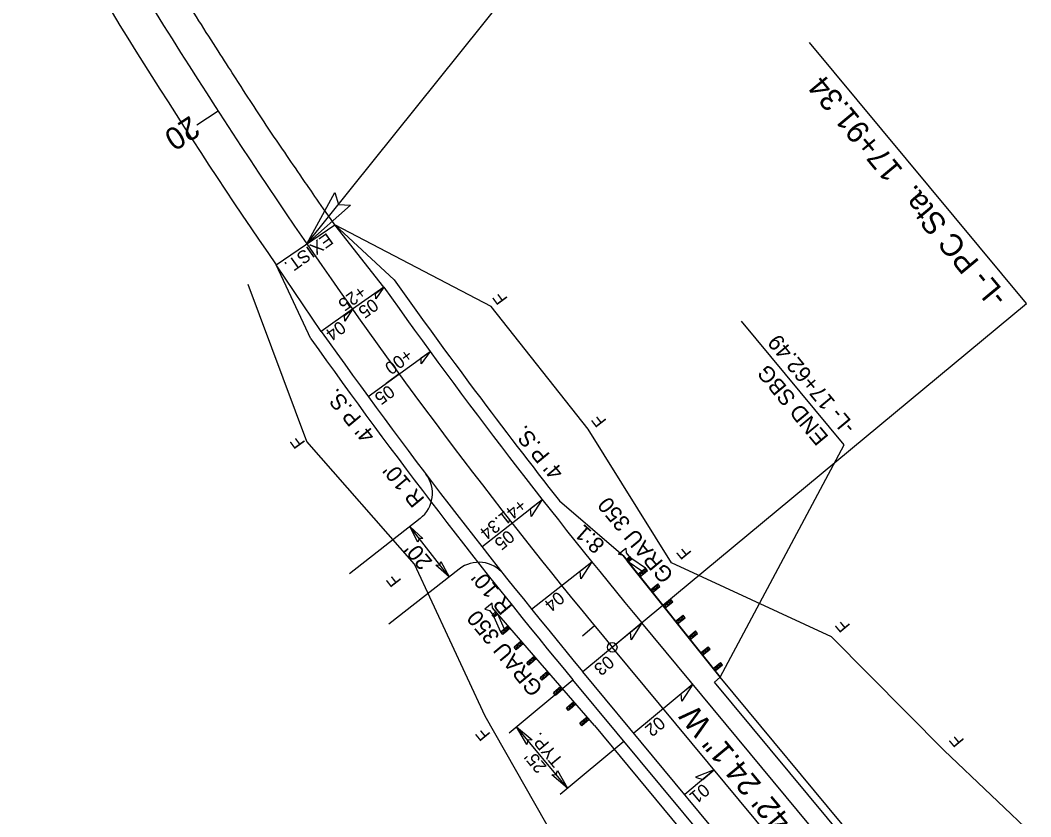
# Model space of a CAD drawing. Extents: x 2597570 to 2598622, y 852675 to 853890.
# Drawn here: x 2597705.3 to 2598022, y 853396.2 to 853645.9 of the extents above; entities that cross this region are included whole.
import ezdxf

# ---------------------------------------------------------------- set-up
doc = ezdxf.new("R2010")
doc.units = 0
for name, color, linetype in [('Exist Drainage Structure Bridge Pier Bent Interior', 7, 'Continuous'), ('Exist Hydrographic Channel Edge', 7, 'Continuous'), ('Exist Plan Preparation Drainage Arrows Symbol CELL', 7, 'Continuous'), ('Exist Plan Preparation Watershed Blue', 7, 'Continuous'), ('Exist Structure Major Deck Tunnel Box Culvert', 7, 'Continuous'), ('Prop Drainage Structure Box Number Symbol CELL', 7, 'Continuous'), ('Prop Drainage Structure Drop Inlet Grate 2 Narrow Slots and Flat Grates 840 29 Label', 7, 'Continuous'), ('Prop Drainage Structure Pipe Alternate 15in', 7, 'Continuous'), ('Prop Drainage Structure Pipe Alternate 15in Label', 7, 'Continuous'), ('Prop Drainage Structure Pipe RCP 15in Class IV', 7, 'Continuous'), ('Prop Drainage Structure Pipe RCP 15in Class IV Label', 7, 'Continuous'), ('Prop Drainage Structure Plot Symbol 20 Scale', 7, 'Continuous'), ('Prop Drainage Structure Plot Symbol 50 Scale', 7, 'Continuous'), ('Prop Earthen Structure Base Ditch Berm Detail Label', 7, 'Continuous'), ('Prop Earthen Structure Ditch Flow Line', 7, 'Continuous'), ('Prop Erosion Rip Rap Pad at Outlet CELL', 7, 'Continuous'), ('Prop Erosion Rip Rap Pad at Outlet Label', 7, 'Continuous'), ('Prop Plan Preparation Crest', 7, 'Continuous'), ('Prop Plan Preparation Sketches Hydraulic Ditch', 7, 'Continuous'), ('Raster_Level_0', 7, 'Continuous')]:
    doc.layers.add(name, color=color, linetype=linetype)

msp = doc.modelspace()

# ---------------------------------------------------------------- linework, layer by layer
at = {"layer": 'Exist Drainage Structure Bridge Pier Bent Interior'}
for p, q in [((2598020.66, 853557.15), (2597952.72, 853638.96)), ((2597892, 853450.31), (2598020.66, 853557.15))]:
    msp.add_line(p, q, dxfattribs=at)
msp.add_circle((2597890.84, 853449.35), 1.5, dxfattribs=at)
at = {"layer": 'Exist Hydrographic Channel Edge'}
msp.add_line((2598276.51, 852984.93), (2597890.84, 853449.35), dxfattribs=at)
msp.add_line((2598276.51, 852984.93), (2597890.84, 853449.35), dxfattribs=at)
msp.add_arc((2599247.12, 854575.63), 1762.95, 209.28143, 219.70669, dxfattribs=at)
msp.add_arc((2599247.12, 854575.63), 1762.95, 209.28143, 219.70669, dxfattribs=at)
at = {"layer": 'Exist Plan Preparation Drainage Arrows Symbol CELL'}
for p, q in [((2597824.05, 853535.03), (2597820.01, 853532.08)), ((2597885.33, 853456.03), (2597881.47, 853452.85))]:
    msp.add_line(p, q, dxfattribs=at)
at = {"layer": 'Exist Plan Preparation Watershed Blue'}
for p, q in [((2597892.84, 853478.5), (2597895.11, 853480.37)), ((2597895.11, 853480.37), (2597895.2, 853478.92)), ((2597894.26, 853478.14), (2597892.84, 853478.5)), ((2597895.56, 853476.56), (2597894.26, 853478.14)), ((2597895.2, 853478.92), (2597896.5, 853477.34)), ((2597895.21, 853476.88), (2597896.38, 853477.82)), ((2597895.21, 853476.88), (2597897.01, 853477.03)), ((2597924.66, 853439.93), (2597895.52, 853476.49)), ((2597896.03, 853476.95), (2597895.56, 853476.56)), ((2597896.38, 853477.82), (2597895.83, 853476.1)), ((2597895.83, 853476.1), (2597897.01, 853477.03)), ((2597896.5, 853477.34), (2597896.03, 853476.95)), ((2597897.01, 853477.03), (2597896.38, 853477.82)), ((2597897.01, 853477.03), (2597896.7, 853477.42)), ((2597901.28, 853474.18), (2597897.01, 853477.03)), ((2597900.09, 853473.22), (2597895.83, 853476.1)), ((2597898.89, 853472.27), (2597901.28, 853474.18)), ((2597899.51, 853471.48), (2597901.91, 853473.39)), ((2597900.09, 853473.22), (2597901.91, 853473.39)), ((2597901.28, 853474.18), (2597900.71, 853472.44)), ((2597901.91, 853473.39), (2597901.28, 853474.18)), ((2597900.71, 853472.44), (2597898.89, 853472.27)), ((2597899.51, 853471.48), (2597900.09, 853473.22)), ((2597900.71, 853472.44), (2597900.09, 853473.22)), ((2597902.82, 853467.34), (2597905.16, 853469.21)), ((2597904.61, 853467.49), (2597902.82, 853467.34)), ((2597903.44, 853466.56), (2597905.79, 853468.43)), ((2597903.44, 853466.56), (2597903.99, 853468.27)), ((2597903.99, 853468.27), (2597905.79, 853468.43)), ((2597904.61, 853467.49), (2597903.99, 853468.27)), ((2597905.16, 853469.21), (2597904.61, 853467.49)), ((2597905.79, 853468.43), (2597905.16, 853469.21)), ((2597906.74, 853462.41), (2597909.2, 853464.37)), ((2597909.2, 853464.37), (2597908.59, 853462.61)), ((2597909.82, 853463.58), (2597909.2, 853464.37)), ((2597853.19, 853463.15), (2597850.93, 853461.27)), ((2597850.93, 853461.27), (2597852.34, 853460.91)), ((2597852.34, 853460.91), (2597853.65, 853459.34)), ((2597853.28, 853461.7), (2597853.19, 853463.15)), ((2597854.59, 853460.12), (2597853.28, 853461.7)), ((2597908.59, 853462.61), (2597906.74, 853462.41)), ((2597907.37, 853461.63), (2597909.82, 853463.58)), ((2597907.37, 853461.63), (2597907.97, 853463.39)), ((2597907.97, 853463.39), (2597909.82, 853463.58)), ((2597908.59, 853462.61), (2597907.97, 853463.39)), ((2597854.34, 853460.53), (2597853.2, 853459.55)), ((2597853.2, 853459.55), (2597854.99, 853459.77)), ((2597853.86, 853458.79), (2597853.2, 853459.55)), ((2597853.86, 853458.79), (2597853.53, 853459.17)), ((2597853.65, 853459.34), (2597854.12, 853459.73)), ((2597854.34, 853460.53), (2597853.86, 853458.79)), ((2597854.99, 853459.77), (2597853.86, 853458.79)), ((2597855.88, 853454.06), (2597853.86, 853458.79)), ((2597854.12, 853459.73), (2597854.59, 853460.12)), ((2597885.25, 853424.79), (2597854.67, 853460.15)), ((2597857.04, 853455.06), (2597854.99, 853459.77)), ((2597910.67, 853457.48), (2597913.05, 853459.38)), ((2597912.48, 853457.65), (2597910.67, 853457.48)), ((2597911.3, 853456.7), (2597910.67, 853457.48)), ((2597911.3, 853456.7), (2597913.67, 853458.59)), ((2597911.3, 853456.7), (2597911.86, 853458.43)), ((2597911.86, 853458.43), (2597913.67, 853458.59)), ((2597912.48, 853457.65), (2597911.86, 853458.43)), ((2597913.05, 853459.38), (2597912.48, 853457.65)), ((2597913.67, 853458.59), (2597913.05, 853459.38)), ((2597858.2, 853456.06), (2597855.88, 853454.06)), ((2597858.85, 853455.31), (2597856.54, 853453.3)), ((2597857.04, 853455.06), (2597856.54, 853453.3)), ((2597858.85, 853455.31), (2597857.04, 853455.06)), ((2597857.69, 853454.31), (2597857.04, 853455.06)), ((2597857.69, 853454.31), (2597858.2, 853456.06)), ((2597914.6, 853452.56), (2597916.98, 853454.46)), ((2597916.98, 853454.46), (2597916.42, 853452.73)), ((2597917.61, 853453.67), (2597916.98, 853454.46)), ((2597855.88, 853454.06), (2597857.69, 853454.31)), ((2597856.54, 853453.3), (2597855.88, 853454.06)), ((2597862.32, 853451.3), (2597860.05, 853449.34)), ((2597861.84, 853449.56), (2597862.32, 853451.3)), ((2597916.42, 853452.73), (2597914.6, 853452.56)), ((2597915.22, 853451.77), (2597917.61, 853453.67)), ((2597915.22, 853451.77), (2597915.79, 853453.51)), ((2597915.79, 853453.51), (2597917.61, 853453.67)), ((2597916.42, 853452.73), (2597915.79, 853453.51)), ((2597860.05, 853449.34), (2597861.84, 853449.56)), ((2597860.71, 853448.58), (2597860.05, 853449.34)), ((2597862.98, 853450.54), (2597860.71, 853448.58)), ((2597861.19, 853450.32), (2597860.71, 853448.58)), ((2597862.98, 853450.54), (2597861.19, 853450.32)), ((2597861.84, 853449.56), (2597861.19, 853450.32)), ((2597918.53, 853447.63), (2597920.92, 853449.53)), ((2597919.15, 853446.85), (2597921.54, 853448.75)), ((2597919.15, 853446.85), (2597919.72, 853448.58)), ((2597919.72, 853448.58), (2597921.54, 853448.75)), ((2597920.34, 853447.8), (2597919.72, 853448.58)), ((2597920.92, 853449.53), (2597920.34, 853447.8)), ((2597921.54, 853448.75), (2597920.92, 853449.53)), ((2597866.44, 853446.53), (2597864.07, 853444.48)), ((2597867.1, 853445.78), (2597864.72, 853443.72)), ((2597865.26, 853445.51), (2597864.72, 853443.72)), ((2597867.1, 853445.78), (2597865.26, 853445.51)), ((2597865.91, 853444.75), (2597865.26, 853445.51)), ((2597865.91, 853444.75), (2597866.44, 853446.53)), ((2597920.34, 853447.8), (2597918.53, 853447.63)), ((2597864.07, 853444.48), (2597865.91, 853444.75)), ((2597864.72, 853443.72), (2597864.07, 853444.48)), ((2597870.56, 853441.77), (2597868.27, 853439.78)), ((2597870.07, 853440.02), (2597870.56, 853441.77)), ((2597871.22, 853441.01), (2597870.56, 853441.77)), ((2597922.46, 853442.7), (2597924.8, 853444.57)), ((2597922.46, 853442.7), (2597923.63, 853443.64)), ((2597924.25, 853442.86), (2597922.46, 853442.7)), ((2597923.08, 853441.92), (2597922.46, 853442.7)), ((2597923.08, 853441.92), (2597925.42, 853443.79)), ((2597923.63, 853443.64), (2597923.08, 853441.92)), ((2597923.63, 853443.64), (2597925.42, 853443.79)), ((2597924.25, 853442.86), (2597923.63, 853443.64)), ((2597924.8, 853444.57), (2597924.25, 853442.86)), ((2597925.42, 853443.79), (2597924.8, 853444.57)), ((2597868.27, 853439.78), (2597870.07, 853440.02)), ((2597868.92, 853439.02), (2597868.27, 853439.78)), ((2597871.22, 853441.01), (2597868.92, 853439.02)), ((2597869.42, 853440.77), (2597868.92, 853439.02)), ((2597871.22, 853441.01), (2597869.42, 853440.77)), ((2597870.07, 853440.02), (2597869.42, 853440.77)), ((2597874.69, 853437), (2597872.38, 853435.01)), ((2597875.34, 853436.24), (2597873.04, 853434.25)), ((2597873.53, 853436), (2597873.04, 853434.25)), ((2597875.34, 853436.24), (2597873.53, 853436)), ((2597874.19, 853435.25), (2597873.53, 853436)), ((2597874.19, 853435.25), (2597874.69, 853437)), ((2597872.38, 853435.01), (2597874.19, 853435.25)), ((2597873.04, 853434.25), (2597872.38, 853435.01)), ((2597878.81, 853432.23), (2597876.5, 853430.24)), ((2597878.31, 853430.48), (2597878.81, 853432.23)), ((2597876.5, 853430.24), (2597878.31, 853430.48)), ((2597877.15, 853429.48), (2597876.5, 853430.24)), ((2597879.46, 853431.48), (2597877.15, 853429.48)), ((2597877.65, 853431.24), (2597877.15, 853429.48)), ((2597879.46, 853431.48), (2597877.65, 853431.24)), ((2597878.31, 853430.48), (2597877.65, 853431.24)), ((2597882.93, 853427.47), (2597880.66, 853425.5)), ((2597883.58, 853426.71), (2597881.32, 853424.75)), ((2597881.79, 853426.49), (2597881.32, 853424.75)), ((2597882.93, 853427.47), (2597881.79, 853426.49)), ((2597881.79, 853426.49), (2597883.58, 853426.71)), ((2597882.45, 853425.73), (2597881.79, 853426.49)), ((2597882.45, 853425.73), (2597882.93, 853427.47)), ((2597883.58, 853426.71), (2597882.93, 853427.47)), ((2597880.66, 853425.5), (2597882.45, 853425.73)), ((2597881.32, 853424.75), (2597880.66, 853425.5))]:
    msp.add_line(p, q, dxfattribs=at)
at = {"layer": 'Prop Drainage Structure Box Number Symbol CELL'}
for points in [[(2597808.78, 853587.91), (2597795.11, 853575.8), (2597803.93, 853591.93), (2597804.99, 853588.14)], [(2597829.95, 853482.34), (2597827.35, 853487.16), (2597831.46, 853483.48), (2597830.28, 853483.43)], [(2597837.1, 853476.25), (2597839.7, 853471.42), (2597835.59, 853475.1), (2597836.77, 853475.15)], [(2597864.05, 853418.91), (2597860.86, 853424.45), (2597865.76, 853420.29), (2597864.39, 853420.19)], [(2597873.64, 853410.75), (2597876.83, 853405.21), (2597871.92, 853409.37), (2597873.29, 853409.47)]]:
    msp.add_lwpolyline(points, close=True, dxfattribs=at)
at = {"layer": 'Prop Drainage Structure Drop Inlet Grate 2 Narrow Slots and Flat Grates 840 29 Label'}
for points in [[(2597819.22, 853562.26), (2597816.76, 853558.58), (2597816.67, 853560.27)], [(2597809.43, 853555.31), (2597806.98, 853551.63), (2597806.88, 853553.33)], [(2597833.73, 853542.11), (2597830.99, 853538.25), (2597830.93, 853540.07)], [(2597868.9, 853495.67), (2597865.41, 853490.39), (2597865.26, 853492.81)], [(2597884.46, 853476.1), (2597880.97, 853470.82), (2597880.82, 853473.24)], [(2597900.08, 853457.02), (2597896.73, 853451.65), (2597896.52, 853454.07)], [(2597916.05, 853437.78), (2597912.7, 853432.42), (2597912.49, 853434.83)], [(2597922.79, 853410.88), (2597916.9, 853408.58), (2597919.24, 853407.92)]]:
    msp.add_lwpolyline(points, close=True, dxfattribs=at)
at = {"layer": 'Prop Drainage Structure Pipe Alternate 15in'}
for p, q in [((2597852.93, 853556.15), (2597803.86, 853581.83)), ((2597795.15, 853513.9), (2597776.71, 853563.13))]:
    msp.add_line(p, q, dxfattribs=at)
at = {"layer": 'Prop Drainage Structure Pipe RCP 15in Class IV'}
for p, q in [((2597883.31, 853517.73), (2597852.93, 853556.15)), ((2597909.44, 853475.85), (2597883.31, 853517.73)), ((2597828.81, 853475.45), (2597795.15, 853513.9)), ((2597850.98, 853427.78), (2597828.81, 853475.45)), ((2597959.52, 853452.64), (2597909.44, 853475.85)), ((2597959.52, 853452.64), (2597994.87, 853417.01)), ((2597876.23, 853383.48), (2597850.98, 853427.78)), ((2598031.35, 853382.31), (2597994.87, 853417.01))]:
    msp.add_line(p, q, dxfattribs=at)
at = {"layer": 'Prop Drainage Structure Pipe RCP 15in Class IV Label'}
for p, q in [((2597795.11, 853575.8), (2597947.9, 853766.55)), ((2597839.7, 853471.42), (2597827.35, 853487.16))]:
    msp.add_line(p, q, dxfattribs=at)
msp.add_lwpolyline([(2597924.66, 853439.93), (2597963.56, 853512.8), (2597931.33, 853551.6)], dxfattribs=at)
at = {"layer": 'Prop Drainage Structure Plot Symbol 20 Scale'}
for p, q in [((2597819.22, 853562.26), (2597803.86, 853581.83)), ((2597799.65, 853548.37), (2597785.52, 853569.2)), ((2597830.65, 853489.75), (2597808.51, 853472.37)), ((2597842.82, 853473.87), (2597820.77, 853456.57)), ((2598285.74, 852992.6), (2597900.08, 853457.02)), ((2598267.28, 852977.26), (2597881.61, 853441.69))]:
    msp.add_line(p, q, dxfattribs=at)
for centre, radius, start, end in [((2599247.12, 854575.63), 1774.6, 209.67537, 214.55037), ((2599247.12, 854575.63), 1750.95, 215.36287, 219.70669), ((2599247.12, 854575.63), 1774.95, 215.36287, 219.70669), ((2597824.48, 853497.61), 10, 308.1161, 37.1531), ((2597848.99, 853466), 10, 38.4371, 128.1161)]:
    msp.add_arc(centre, radius, start, end, dxfattribs=at)
msp.add_open_spline([(2597803.86, 853581.83), (2597798.56, 853589.34), (2597793.37, 853596.93), (2597788.17, 853604.52), (2597782.96, 853612.1), (2597777.92, 853619.79), (2597772.94, 853627.54), (2597760.49, 853646.95), (2597748.27, 853666.52), (2597737.11, 853686.69), (2597733.11, 853693.91), (2597729.11, 853701.13), (2597725.12, 853708.35)], degree=3, dxfattribs=at)
at = {"layer": 'Prop Drainage Structure Plot Symbol 50 Scale'}
for p, q in [((2597822.48, 853564.57), (2597803.86, 853581.83)), ((2597796.39, 853546.05), (2597785.52, 853569.2)), ((2597874.34, 853495.21), (2597894.26, 853478.14)), ((2597946.51, 853357.27), (2597878.54, 853439.13)), ((2597997.3, 853348.81), (2597922.87, 853438.44))]:
    msp.add_line(p, q, dxfattribs=at)
for points in [[(2597894.26, 853478.14), (2597924.66, 853439.93)], [(2597924.66, 853439.93), (2597922.87, 853438.44)]]:
    msp.add_lwpolyline(points, dxfattribs=at)
for radius, end in [(1746.95, 218.20379), (1778.95, 219.70669)]:
    msp.add_arc((2599247.12, 854575.63), radius, 215.36287, end, dxfattribs=at)
at = {"layer": 'Prop Earthen Structure Ditch Flow Line'}
for p, q in [((2597785.52, 853569.2), (2597803.86, 853581.83)), ((2597819.22, 853562.26), (2597809.43, 853555.31)), ((2597809.43, 853555.31), (2597799.65, 853548.37)), ((2597814.36, 853527.95), (2597833.73, 853542.11)), ((2597850.01, 853480.86), (2597868.9, 853495.67)), ((2597865.57, 853461.29), (2597884.46, 853476.1)), ((2597900.08, 853457.02), (2597881.61, 853441.68)), ((2597858.5, 853422.49), (2597878.54, 853439.13)), ((2597916.05, 853437.78), (2597897.59, 853422.45)), ((2597876.83, 853405.21), (2597860.86, 853424.45)), ((2597874.47, 853403.26), (2597894.51, 853419.9)), ((2597922.79, 853410.88), (2597913.56, 853403.22))]:
    msp.add_line(p, q, dxfattribs=at)
at = {"layer": 'Prop Erosion Rip Rap Pad at Outlet CELL'}
for p, q in [((2597924.66, 853439.93), (2597894.26, 853478.14)), ((2597885.25, 853424.79), (2597853.28, 853461.7)), ((2598002.47, 853346.24), (2597924.66, 853439.93)), ((2597885.25, 853424.79), (2597971.69, 853320.69)), ((2597917.82, 853416.87), (2597917.82, 853416.87))]:
    msp.add_line(p, q, dxfattribs=at)
at = {"layer": 'Prop Plan Preparation Crest'}
msp.add_line((2597767.34, 853617.38), (2597760.63, 853613.03), dxfattribs=at)
at = {"layer": 'Prop Plan Preparation Sketches Hydraulic Ditch'}
msp.add_line((2598014.45, 853331.81), (2597924.66, 853439.93), dxfattribs=at)

# ---------------------------------------------------------------- texts
at = {"layer": 'Exist Drainage Structure Bridge Pier Bent Interior'}
msp.add_text('-L- PC Sta.  17+91.34', height=7, rotation=129.7067, dxfattribs=at).set_placement((2598015.14, 853559.35))
at = {"layer": 'Exist Plan Preparation Watershed Blue'}
for p in [(2597910.37, 853472.06), (2597869.38, 853436.58)]:
    msp.add_text('GRAU 350', height=5, rotation=129.7067, dxfattribs=at).set_placement(p)
at = {"layer": 'Exist Structure Major Deck Tunnel Box Culvert'}
msp.add_text('N 39%%d 42\' 24.1" W', height=7, rotation=129.7067, dxfattribs=at).set_placement((2597963.99, 853375.02))
at = {"layer": 'Prop Drainage Structure Pipe Alternate 15in Label'}
for s, p in [('-L- 17+62.49', (2597967.38, 853518.6)), ('END SBG', (2597958.88, 853515.29))]:
    msp.add_text(s, height=5, rotation=129.7067, dxfattribs=at).set_placement(p)
at = {"layer": 'Prop Earthen Structure Base Ditch Berm Detail Label'}
for rotation, p in [(126.1754, (2597858.26, 853558.64)), (127.8004, (2597889.23, 853520.35)), (126.1754, (2597794.79, 853513.5)), (129.4254, (2597915.93, 853479)), (127.8004, (2597824.92, 853470.24)), (129.7067, (2597965.64, 853456.12)), (129.4254, (2597852.88, 853422.08)), (129.7067, (2598001.36, 853420.14))]:
    msp.add_text('F', height=4, rotation=rotation, dxfattribs=at).set_placement(p)
at = {"layer": 'Prop Earthen Structure Ditch Flow Line'}
for s, rotation, p in [('EXIST.', 215.3629, (2597801.49, 853579.45)), ('+25', 215.3629, (2597811.95, 853562.98)), ('05', 215.3629, (2597815.7, 853558.9)), ('04', 215.3629, (2597805.48, 853551.88)), ('+00', 216.9879, (2597826.4, 853543.19)), ('05', 216.1754, (2597820.76, 853531.8)), ('+41.34', 218.0818, (2597861.99, 853496.13)), ('05', 219.7067, (2597858.11, 853486.36)), ('04', 219.7159, (2597873.78, 853467.11)), ('03', 219.7159, (2597889.32, 853447.01)), ('02', 219.7159, (2597905.33, 853427.91)), ('TYP.', 129.7067, (2597875.7, 853413.88)), ("25'", 129.7067, (2597870.49, 853411.92)), ('01', 219.7159, (2597919.27, 853406.88))]:
    msp.add_text(s, height=4, rotation=rotation, dxfattribs=at).set_placement(p)
at = {"layer": 'Prop Erosion Rip Rap Pad at Outlet Label'}
for s, rotation, p in [("4' P.S.", 129.7067, (2597816.86, 853515.96)), ("4' P.S.", 129.7067, (2597875.93, 853504.4)), ("R 10'", 129.7067, (2597832.26, 853495.82)), ('8:1', 138.494, (2597888.85, 853481.98)), ("20'", 129.7067, (2597834.71, 853476.25)), ("R 10'", 129.7067, (2597859.97, 853462.18))]:
    msp.add_text(s, height=5, rotation=rotation, dxfattribs=at).set_placement(p)
at = {"layer": 'Raster_Level_0'}
msp.add_text('20', height=7, rotation=212.9254, dxfattribs=at).set_placement((2597758.56, 853616.2))

doc.saveas('drawing.dxf')
